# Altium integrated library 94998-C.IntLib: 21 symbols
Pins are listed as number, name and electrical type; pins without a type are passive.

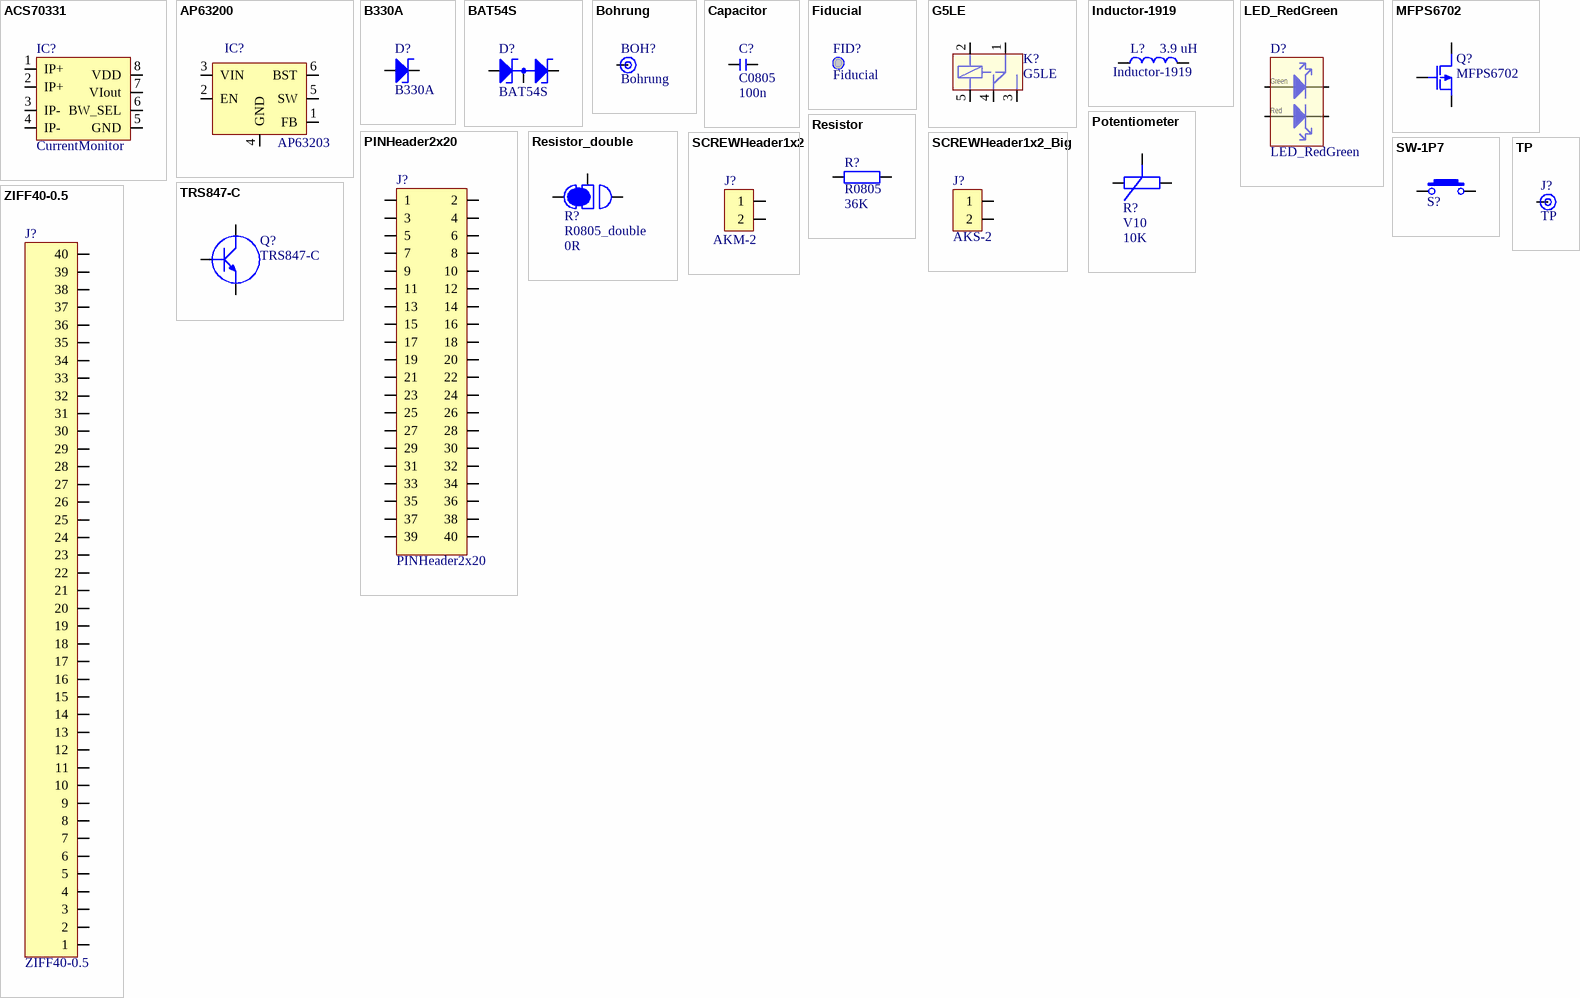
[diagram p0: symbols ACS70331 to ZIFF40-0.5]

## ACS70331
designator IC?, comment CurrentMonitor
High Sensitivity, 1 MHz, GMR-Based Current Sensor IC; Vendor1: Allegro microsystems; Vendor1_PN: ACS70331EOLCTR-005U3; Vendor2_PN: ACS722LLCTR-05AB-T
footprint SOIC8_current (SOIC, 8-Leads, Body 4,9x3,9mm (max), Pitch 1,27mm, KeepOut)
pins: 1 IP+, 2 IP+, 3 IP-, 4 IP-, 5 GND, 6 BW_SEL, 7 VIout, 8 VDD

## AP63200
designator IC?, comment AP63203
Vendor1: Diodes Incorporated; Vendor1_PN: AP63203WU-7
footprint TSOT26 (6 pin 0.95 pitch)
pins: 1 FB, 2 EN, 3 VIN, 4 GND, 5 SW, 6 BST

## B330A
designator D?
Schottky; EA_PN: DIODESB330A; Vendor1_PN: B330A-13-F
footprint SMA (Molded Diode, 2-Leads, Body 4.3x2.6mm, IPC Low Density)
pins: 1 A, 2 C

## BAT54S
designator D?
Vendor1: ROHM Semiconductor; Vendor2: Diodes Incorporated; Vendor1_PN: BAT54SHMFHT116; Vendor2_PN: BAT54S-7-F; Value: BAT54S-7-F
footprint SOT23-3 (SOT23, 3-Leads, Body 3,0x2,5mm (max), Pitch 0,95mm, IPC Medium Density)
pins: 1 A, 2 C, 3 A/C

## Bohrung
designator BOH?  (no BOM)
footprint BOH_M3 (Bohrung 6.5 / 3.5 mm)
footprint BOH_35 (Bohrung 4.0 / 3.5 mm)
footprint BOH_F111_01 (Bohrung 1.1 / 0.9 mm)
footprint Standoff_6 (SMD Standoff 6mm height)
footprint BOH_3_2 (Bohrung 6.5 / 3.2 mm)
pins: 1 (power)

## Capacitor
designator C?  value 100n
Capacitor
footprint C0603 (Chip Capacitor, 2-Leads, Body 1,6x0,8mm, IPC Medium Density)
footprint C0805 (Chip Capacitor, 2-Leads, Body 2,0x1,3mm, IPC Medium Density)
footprint C1206 (Chip Capacitor, 2-Leads, Body 2 IPC Medium Density)
footprint C1210 (Chip Capacitor, 2-Leads, Body 3,2x2,5mm, IPC Medium Density)
footprint C1812
pins: 1, 2

## Fiducial
designator FID?  (no BOM)
footprint Fiducial

## G5LE
designator K?
Relais; Vendor1: Omron; Vendor1_PN: G5LE-1-ASI DC3
footprint G5LE (Relais)
pins: 1 in, 2 coil1, 3 out_off, 4 out_on, 5 coil2

## Inductor-1919
designator L?  value 3.9 uH
Vendor1: Bourns; Vendor2: Würth; Vendor1_PN: SRR4028-3R9; Vendor2_PN: 7440430039
footprint L_1919 (WE-TPC_4828 Power Inductor, SMD, 2-Leads, body 4.8x4.8mm)
pins: 1, 2

## LED_RedGreen
designator D?
LED red green 1210; EA_PN: ZLEDS020-RG; Vendor1: ROHM; Vendor1_PN: SML-020MVTT86
footprint LEDDUO1210 (Duo Led 1210)
pins: 1 C_Green, 2 A_Green, 3 C_Red, 4 A_Red

## MFPS6702
designator Q?
Vendor1: Vishay; Vendor1_PN: IRLMS6702TR-PBF
footprint TSOP-6
pins: 1 D, 3 G, 4 S

## PINHeader2x20
designator J?
Pin strip 2x20
footprint PINHDR2X20 (Stiftleiste)
pins: 1, 2, 3, 4, 5, 6, 7, 8, 9, 10, 11, 12, 13, 14, 15, 16, 17, 18, 19, 20, 21, 22, 23, 24, 25, 26, 27, 28, 29, 30, 31, 32, 33, 34, 35, 36, 37, 38, 39, 40

## Potentiometer
designator R?  value 10K
Potentiometer; EA_PN: POT10K-L; Vendor1: PIHER; Vendor1_PN: PIH PT10MV103IPM
footprint V10 (Potentiometer V10)
pins: 1 A, 2 E, 3 S

## Resistor
designator R?  value 36K
Resistor
footprint R0603 (Chip Resistor, 2-Leads, Body 1,6x0,8mm, IPC Medium Density)
footprint R0805 (Chip Resistor, 2-Leads, Body 2,0x1,3mm, IPC Medium Density)
footprint R0805_NOSOLDER (ohne Lötpaste -> Handlötung)
footprint R1206 (Chip Resistor, 2-Leads, Body 3,1x1,6mm, IPC Medium Density)
footprint R1206_NOSOLDER (ohne Lötpaste -> Handlötung)
pins: 1, 2

## Resistor_double
designator R?  value 0R
Resistor
footprint R0805_double (Chip Resistor, 3-Leads, Body 4,0x1,3mm, IPC Medium Density)
pins: 1, 2, 3

## SCREWHeader1x2
designator J?, comment AKM-2
Screw terminal 1x2
footprint SCREWHDR1X2 (Klemmleiste)
footprint SCREWHDR1X2-Mirror (Klemmleiste)
pins: 1, 2

## SCREWHeader1x2_Big
designator J?, comment AKS-2
Screw terminal 1x2
footprint SCREWHDR1X2_Big (AKM-2)
pins: 1, 2

## SW-1P7
designator S?, comment SMD Taster  (value not drawn)
Switch, Knackfrosch; EA_PN: TASTS-1P7MM; Vendor1: DIPTRINICS MANUFACTURING; Vendor1_PN: DTSM63N
footprint TASTER_SMD (TASTS-1P7MM)
pins: 1, 2

## TP
designator J?  (no BOM)
footprint PAD06/15
footprint PAD44/74
footprint PAD50/65 (Oszi_Klammer passt)
pins: 1 (power)

## TRS847-C
designator Q?
Vendor1: MICRONETIC; Vendor1_PN: BC 847-C SOT23
footprint SOT23-3 (SOT23, 3-Leads, Body 3,0x2,5mm (max), Pitch 0,95mm, IPC Medium Density)
pins: 1 B, 2 E, 3 C

## ZIFF40-0.5
designator J?
EA_PN: WF050-40S (Bottom contact) / WF050-40ST (Top contact); Vendor1: Neltron; Vendor2: Würth; Vendor1_PN: 1226-40-02 (Bottom contact) / 1226-40-03 (Top contact); Vendor2_PN: 68714014522 (Bottom contact) / 68714014022 (Top contact)
footprint ZIFF40-0.5 (Ziff Stecker 0.5 pitch 40 pins)
footprint ZIFF40-0.5-Mirror (Ziff Stecker 0.5 pitch 40 pins)
footprint ZIFF40-0.5 - LONG (Ziff Stecker 0.5 pitch 40 pins)
pins: 1, 2, 3, 4, 5, 6, 7, 8, 9, 10, 11, 12, 13, 14, 15, 16, 17, 18, 19, 20, 21, 22, 23, 24, 25, 26, 27, 28, 29, 30, 31, 32, 33, 34, 35, 36, 37, 38, 39, 40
